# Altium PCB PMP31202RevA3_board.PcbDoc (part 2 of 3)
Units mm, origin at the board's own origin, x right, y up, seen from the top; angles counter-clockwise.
Board outline 156.21 x 130.81 mm, 4 copper layers (Top Layer, Layer 2, Layer 3, Bottom Layer), stack 1.671 mm thick; 198 components, 74 nets, 489 pads, 691 vias.
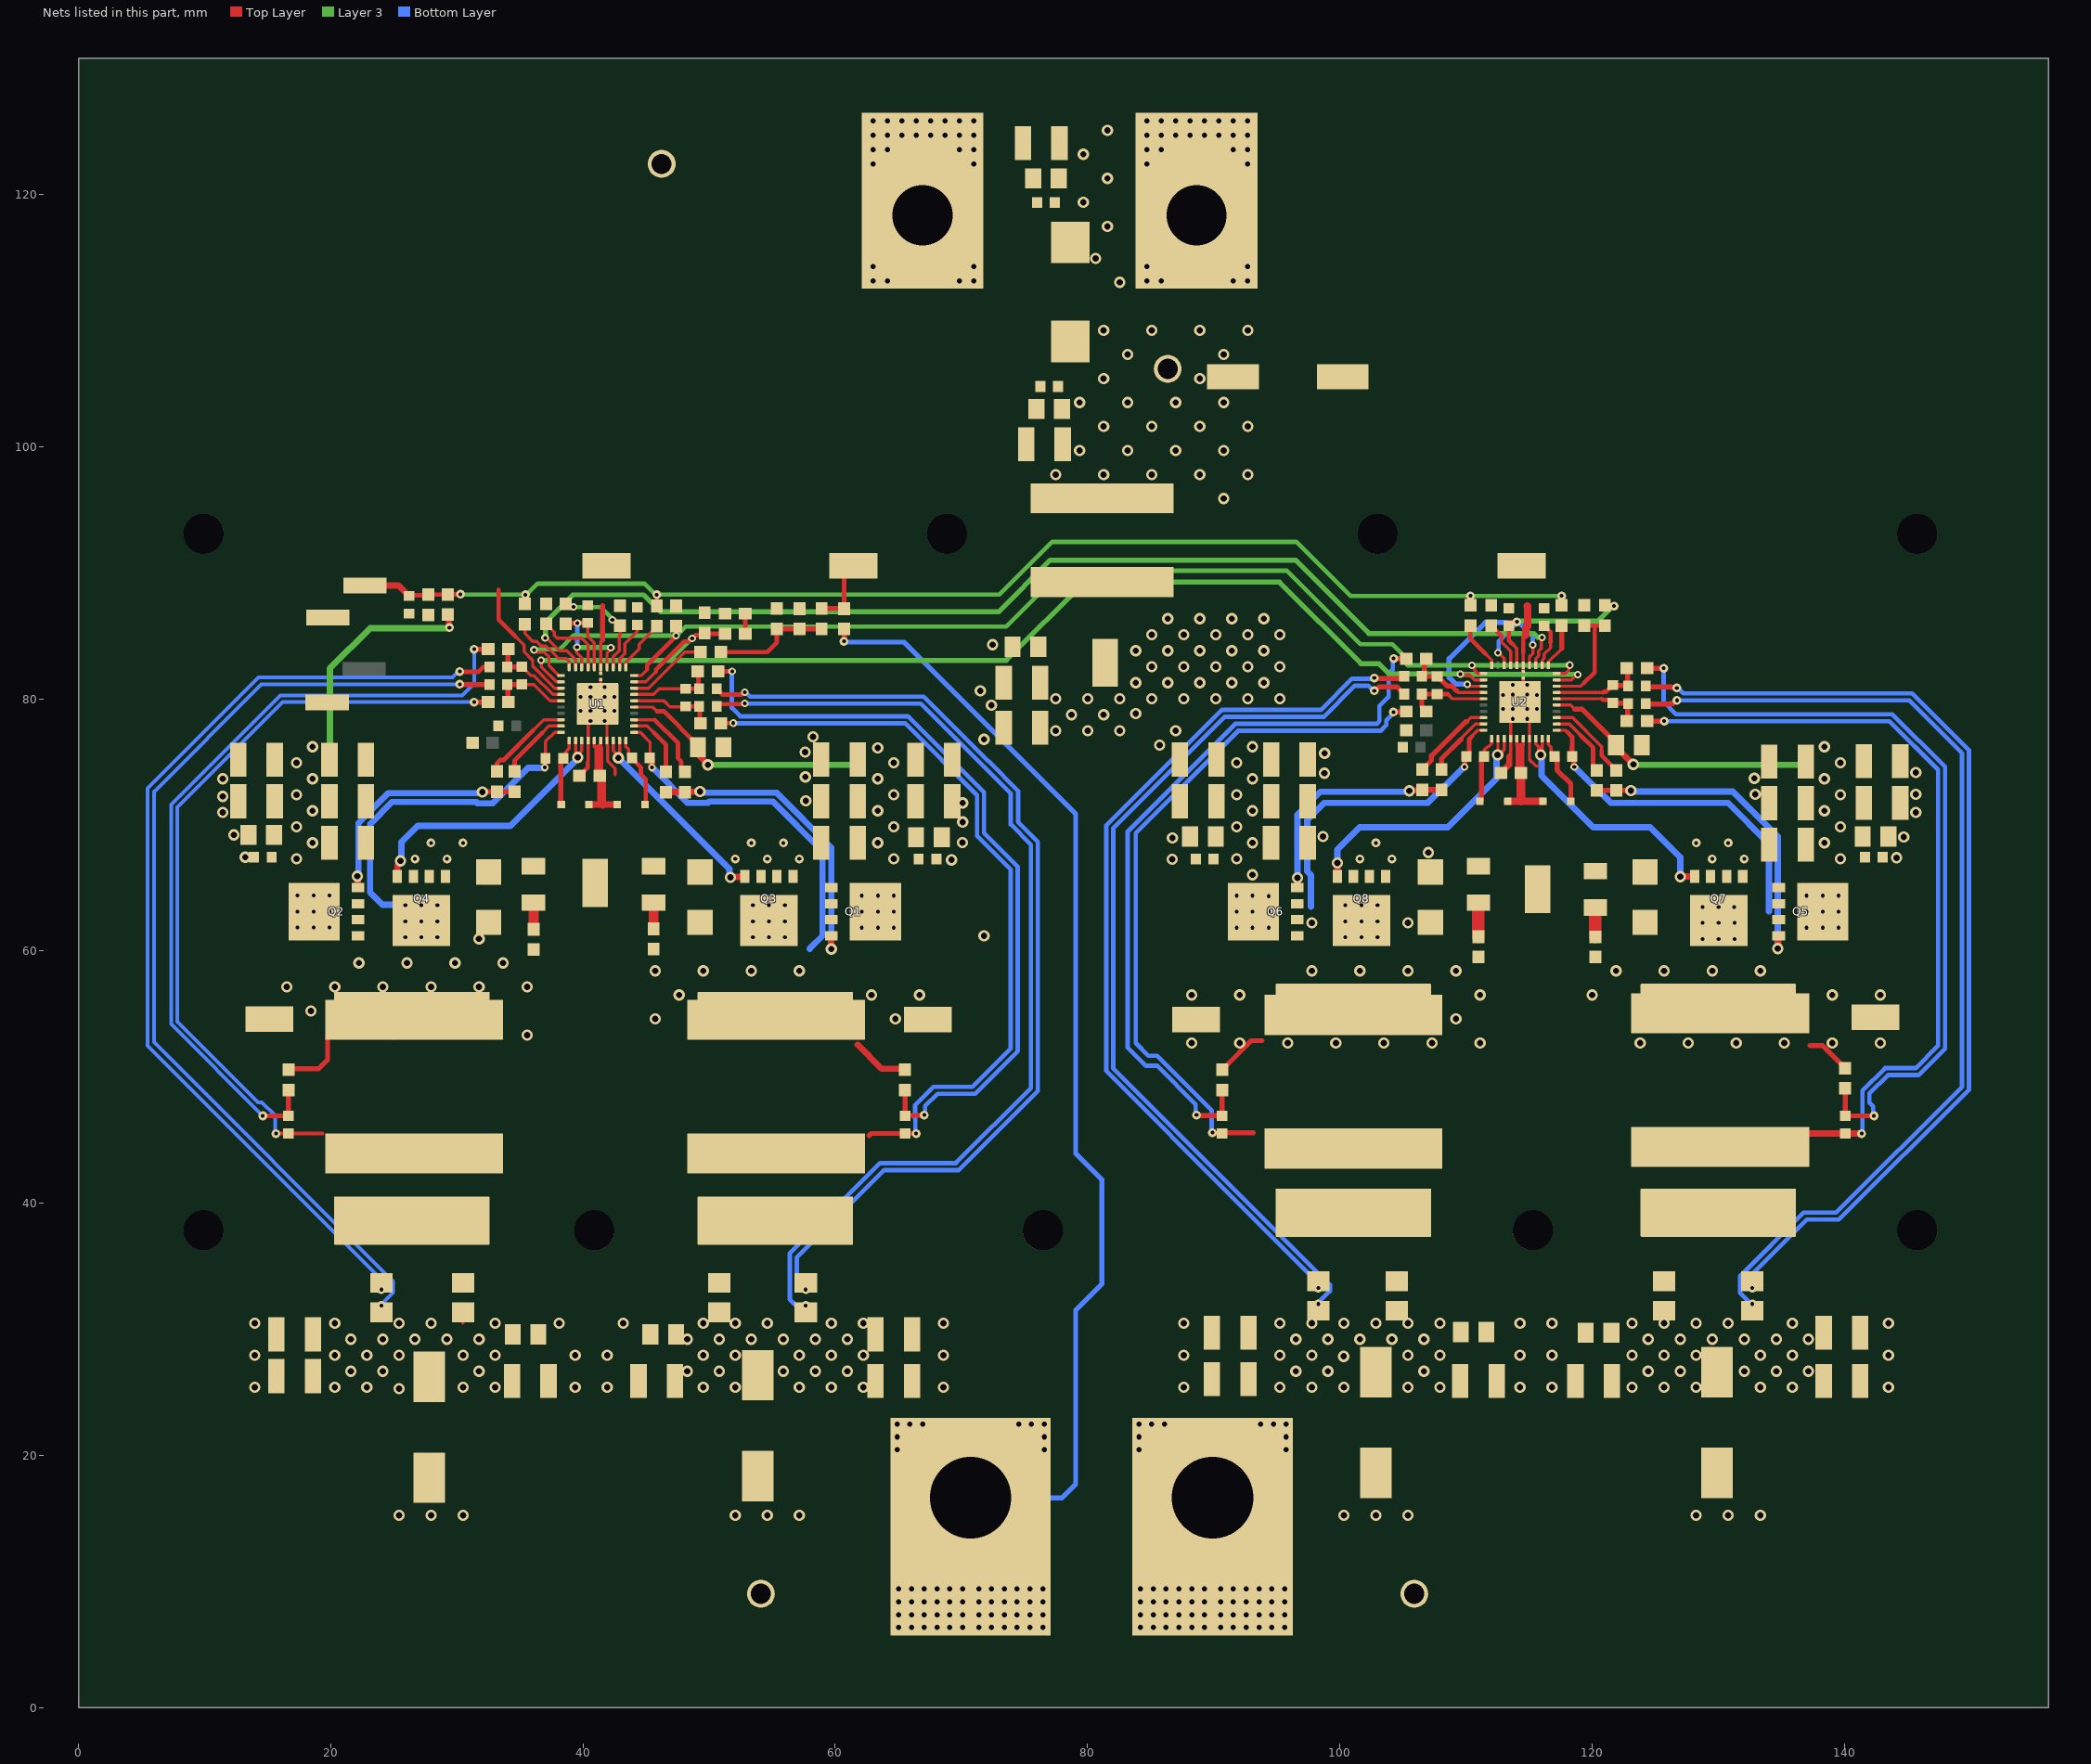
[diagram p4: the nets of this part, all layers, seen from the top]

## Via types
v1: diameter 0.9, hole 0.5, Top Layer to Bottom Layer, tented bottom, 173 vias
v2: diameter 0.813, hole 0.406, Top Layer to Bottom Layer, 172 vias
v3: diameter 0.9, hole 0.5, Top Layer to Bottom Layer, 82 vias
v4: diameter 0.9, hole 0.5, Top Layer to Bottom Layer, tented both sides, 73 vias
v5: diameter 0.7, hole 0.3, Top Layer to Bottom Layer, 69 vias
v6: diameter 0.7, hole 0.3, Top Layer to Bottom Layer, tented bottom, 28 vias
v7: diameter 0.6, hole 0.3, Top Layer to Bottom Layer, tented both sides, 26 vias
v8: diameter 0.7, hole 0.3, Top Layer to Bottom Layer, tented both sides, 24 vias
v9: diameter 0.6, hole 0.3, Top Layer to Bottom Layer, 24 vias
v10: diameter 0.9, hole 0.5, Top Layer to Bottom Layer, tented top, 13 vias
v11: diameter 0.7/0.7/0.7/0.7 (per signal layer), hole 0.3, Top Layer to Bottom Layer, tented bottom, 2 vias
v12: diameter 0.7/0.7/0.7/0.7 (per signal layer), hole 0.3, Top Layer to Bottom Layer, tented both sides, 2 vias
v13: diameter 0.7, hole 0.3, Top Layer to Bottom Layer, tented top, 1 vias
v14: diameter 0.7, hole 0.4, Top Layer to Bottom Layer, tented both sides, 1 vias
v15: diameter 0.6, hole 0.3, Top Layer to Bottom Layer, tented top, 1 vias

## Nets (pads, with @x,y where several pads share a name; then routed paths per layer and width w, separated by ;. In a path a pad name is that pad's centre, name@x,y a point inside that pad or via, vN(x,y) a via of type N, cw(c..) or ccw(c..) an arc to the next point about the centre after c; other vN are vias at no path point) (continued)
AGND1: C13.1 C47.2 C48.2 C49.2 C50.2 C52.2 NT1.2 R25.2 R29.1 R30.1 TP6.1 U1.3 U1.35 | length 15.6
  Top Layer w0.25: 34.627,84.949 35.317,84.26 35.317,83.751 36.007,83.061 36.007,82.588 37.749,80.846 U1.3@38.248,80.846 ; NT1.2@41.402,82.042 U1.35@41.398,82.496 41.398,84.523 41.533,84.658
  Top Layer w0.35: 33.298,88.666 33.298,86.279 34.627,84.949
  Top Layer w0.4: 41.533,84.658 41.533,87.4
AGND2: C55.1 C89.2 NT2.2 R54.2 R55.1 TP8.1 U2.35 | length 5.3
  Top Layer w0.25: 114.55,83.656 U2.35@114.55,82.656 114.55,82.169 NT2.2@114.554,82.169
  Top Layer w0.35: 114.55,83.656 114.55,84.861 114.753,85.064
  Top Layer w0.6: 114.753,85.064 114.753,85.611 114.896,85.754 114.896,87.341 114.875,87.362
COMP: C47.1 R28.2 U1.2 U1.29 U2.2 U2.29 | length 105.7
  Top Layer w0.25: v7(36.673,83.061) 36.703,83.031 36.703,82.528 37.886,81.346 U1.2@38.248,81.346 ; U1.29@44.048,81.346 44.974,81.346 45.777,82.149 ; v7(109.577,81.965) 109.644,81.898 110.286,81.898 110.678,81.506 U2.2@111.4,81.506 ; U2.29@117.2,81.506 118.368,81.506 118.777,81.915 v7(118.872,81.915)
  Top Layer w0.35: 45.777,82.149 45.777,82.321 48.014,84.558 48.356,84.558 48.594,84.796 v7(48.648,84.796) 48.664,84.796 48.918,85.05 49.469,85.05 C47.1@49.643,85.224 49.714,85.153 51.245,85.153 R28.2@51.26,85.168
  Layer 3 w0.4: v7(36.673,83.061) 46.859,83.061 ; v7(48.648,84.796) 48.594,84.796 46.859,83.061 ; v7(118.872,81.915) 118.847,81.94 109.602,81.94 v7(109.577,81.965) 103.927,81.965 103.092,82.8 101.688,82.8 95.23,89.258 79.755,89.258 73.558,83.061 46.859,83.061
NetC1_1: C1.1 C2.2 C3.2 J1.1 L1.1
  other v1: 81.577,121.285 79.672,123.19 81.577,125.095
  other v2: 84.709,113.157 85.852,113.157 91.567,113.157 92.71,113.157 84.709,114.3 92.71,114.3 84.709,122.428 92.71,122.428 84.709,123.571 85.852,123.571 91.567,123.571 92.71,123.571 84.709,124.714 85.852,124.714 86.995,124.714 88.138,124.714 89.281,124.714 90.424,124.714 91.567,124.714 92.71,124.714 84.709,125.857 85.852,125.857 86.995,125.857 88.138,125.857 89.281,125.857 90.424,125.857 91.567,125.857 92.71,125.857
  other v4: 82.55,113.03 80.645,114.935 81.577,117.475 79.672,119.38
NetC4_2: C4.2 C5.2 C6.1 C7.1 L1.2 L2.1 TP1.1
  other v1: 90.805,95.885 88.9,97.79 92.71,97.79 83.185,99.695 86.995,99.695 90.805,99.695 81.28,101.6 85.09,101.6 88.9,101.6 83.185,103.505 86.995,103.505 81.28,105.41 83.185,107.315 85.09,109.22 88.9,109.22
  other v4: 77.47,97.79 81.28,97.79 85.09,97.79 79.375,99.695 92.71,101.6 79.375,103.505 90.805,103.505 88.9,105.41 90.805,107.315 81.28,109.22 92.71,109.22
NetC29_1: C29.1 C32.1 D3.1 L3.2 Q1.1 Q1.2 Q1.3 Q3.5 R8.2 SW1.1 U1.21 | length 32.9
  Top Layer w0.25: U1.21@44.048,77.346 44.545,77.346 45.315,76.576 45.315,75.349 C29.1@45.277,75.311
  Top Layer w0.5: C29.1@45.315,75.349 45.427,75.237 45.427,74.615 45.466,74.576 v7(45.466,74.549) ; 61.775,52.58 63.696,50.659 65.457,50.659 R8.2@65.532,50.584
  Bottom Layer w0.5: v7(45.466,74.549) 45.493,74.549 48.301,71.741 49.9,71.741 50.024,71.864 55.028,71.864 58.989,67.903 58.989,61.214 57.975,60.2 57.975,60.16 ; v5(56.007,63.627) v5@56.035,63.627
  other v3: 45.72,54.61 64.77,54.61 47.625,56.515 62.865,56.515 66.675,56.515 45.72,58.42 49.53,58.42 53.34,58.42 57.15,58.42
  other v5: 53.467,61.087 54.737,61.087 56.007,61.087 53.467,62.357 54.737,62.357 56.007,62.357 53.467,63.627 54.737,63.627
NetC29_2: C29.2 D1.1 U1.20 | length 6.1
  Top Layer w0.25: U1.20@43.398,76.696 43.398,76.204 43.602,76 43.602,75.586 C29.2@43.877,75.311
  Top Layer w0.35: C29.2@44.102,75.086 C29.2@43.877,75.311 43.877,75.286 44.577,74.586 44.577,74.023 44.974,73.626 44.974,71.687 D1.1@44.915,71.628
NetC30_1: C30.1 C33.2 D4.1 L4.2 Q2.1 Q2.2 Q2.3 Q4.5 R9.2 SW2.1 U1.10 | length 42.7
  Top Layer w0.25: C30.1@37.023,75.297 37.023,76.627 37.742,77.346 U1.10@38.248,77.346
  Top Layer w0.4: R9.2@16.667,50.554 R9.2@16.637,50.584 16.712,50.659 19.016,50.659 19.742,51.386 19.742,53.161 21.132,54.551 L4.2@26.409,54.551 ; L4.2@25.019,53.161 L4.2@26.409,54.551 ; L4.2@26.592,54.551 L4.2@26.409,54.551
  Top Layer w0.5: v7(36.957,74.549) 36.976,74.568 36.976,75.25 C30.1@37.023,75.297
  Bottom Layer w0.5: v5(25.908,63.627) 25.87,63.665 24.092,63.665 23.114,64.643 23.114,70.082 24.859,71.828 31.516,71.828 31.639,71.705 32.803,71.705 35.628,74.53 36.938,74.53 v7(36.957,74.549)
  other v3: 35.56,53.34 18.415,55.245 16.51,57.15 35.56,57.15 22.225,59.055 26.035,59.055 29.845,59.055 33.655,59.055
  other v5: 25.908,61.087 27.178,61.087 28.448,61.087 25.908,62.357 27.178,62.357 28.448,62.357 27.178,63.627 28.448,63.627
  other v10: 20.32,57.15 24.13,57.15 27.94,57.15 31.75,57.15 31.75,60.96
NetC30_2: C30.2 D2.1 U1.11 | length 5.4
  Top Layer w0.25: C30.2@38.423,75.297 38.598,75.472 38.598,75.772 38.898,76.072 U1.11@38.898,76.696
  Top Layer w0.4: D2.1@38.27,71.628 38.223,71.675 38.223,75.097 C30.2@38.423,75.297
NetC31_1: C31.1 R8.1 R15.2 | length 61.9
  Top Layer w0.35: R15.2@50.701,82.188 50.711,82.178 51.807,82.178 v7(51.816,82.169) ; C31.1@65.532,46.928 65.563,46.959 67.025,46.959 v8(67.056,46.99)
  Top Layer w0.4: C31.1@65.532,46.928 R8.1@65.532,48.984
  Bottom Layer w0.35: v7(51.816,82.169) 51.801,82.154 51.801,79.275 52.462,78.614 65.762,78.614 71.792,72.583 71.792,69.352 74.464,66.68 74.464,52.054 71.094,48.684 68.106,48.684 67.123,47.701 67.123,47.057 v8(67.056,46.99)
NetC31_2: C31.2 L3.1 R6.2 R11.2 R14.2 R61.2 | length 139.8
  Top Layer w0.35: R11.2@50.601,80.791 50.601,80.766 50.826,80.541 50.851,80.541 51.046,80.346 52.592,80.346 52.764,80.518 v7(52.832,80.518) ; R14.2@50.918,78.064 50.924,78.07 51.914,78.07 v7(51.92,78.077) ; v8(57.658,33.147) R6.2@57.658,34.212 ; C31.2@65.532,45.528 v8(66.411,45.528)
  Top Layer w0.4: 62.675,45.353 62.85,45.528 C31.2@65.532,45.528
  Bottom Layer w0.35: v7(51.92,78.077) 51.933,78.064 65.534,78.064 71.242,72.356 71.242,69.124 73.914,66.452 73.914,52.282 70.866,49.234 67.777,49.234 66.331,47.788 66.331,46.69 66.344,46.677 66.344,45.595 v8(66.411,45.528) ; v7(52.832,80.518) 52.898,80.518 53.237,80.179 67.01,80.179 72.134,75.055 72.146,75.055 74.492,72.709 74.492,70.241 76.067,68.665 76.067,48.905 69.792,42.63 63.881,42.63 56.938,35.687 56.938,33.962 57.658,33.242 v8(57.658,33.147)
NetC32_2: C32.2 R18.2 | length 2.1
  Top Layer w0.8: C32.2@45.593,61.76 R18.2@45.593,63.828
NetC33_1: C33.1 R19.1 | length 2.1
  Top Layer w0.8: C33.1@36.068,61.722 R19.1@36.068,63.828
NetC34_1: C34.1 R9.1 R16.2 | length 63.6
  Top Layer w0.4: v6(14.605,46.928) C34.1@16.637,46.928 R9.1@16.637,48.984 ; v8(31.369,83.933) R16.2@32.478,83.933
  Bottom Layer w0.3: v6(14.605,46.928) 7.332,54.201 7.332,71.615 15.983,80.266 30.418,80.266 31.369,81.217 v8(31.369,83.933)
NetC34_2: C34.2 L4.1 R7.1 R12.2 R17.2 R71.1 | length 140.8
  Top Layer w0.3: v6(15.646,45.528) C34.2@16.637,45.528 19.35,45.528 ; v8(24.003,33.147) R7.1@24.003,34.212
  Top Layer w0.35: v8(30.226,82.169) 30.257,82.138 31.68,82.138 32.078,82.536 R12.2@32.578,82.536
  Top Layer w0.4: v8(31.369,79.742) R17.2@32.478,79.742 ; R12.2@32.538,82.496 R12.2@32.578,82.536
  Bottom Layer w0.3: v6(15.646,45.528) 15.57,45.605 15.57,46.953 14.517,48.006 14.234,48.006 7.832,54.408 7.832,71.408 16.166,79.742 v8(31.369,79.742) ; v8@23.936,33.214 23.936,34.02 5.469,52.487 5.469,72.908 14.264,81.703 29.652,81.703 30.118,82.169 v8(30.226,82.169)
  Bottom Layer w0.35: v8@23.936,33.214 v8(24.003,33.147)
NetC45_1: C45.1 R10.1 R14.1 U1.26 | length 6.7
  Top Layer w0.25: U1.26@44.048,79.846 46.422,79.846 46.889,79.379 48.105,79.379 C45.1@48.123,79.397
  Top Layer w0.35: C45.1@48.123,79.397 48.125,79.396 49.199,79.396 R10.1@49.201,79.394 49.26,79.335 49.26,78.123 R14.1@49.318,78.064
NetC45_2: C45.2 R11.1 R15.1 U1.27 | length 6.8
  Top Layer w0.25: U1.27@44.048,80.346 45.581,80.346 46.032,80.797 C45.2@48.123,80.797
  Top Layer w0.35: C45.2@48.123,80.797 48.126,80.794 R11.1@49.198,80.794 ; R15.1@49.101,82.188 49.151,82.138 49.151,80.841 R11.1@49.198,80.794 ; R11.1@49.201,80.791 R11.1@49.198,80.794
NetC46_1: C46.1 R13.1 R17.1 U1.5 | length 6.2
  Top Layer w0.25: C46.1@35.15,81.146 35.157,81.139 36.093,81.139 37.386,79.846 U1.5@38.248,79.846
  Top Layer w0.4: R17.1@34.078,79.742 34.028,79.792 34.028,81.089 R13.1@33.978,81.139 33.982,81.142 35.147,81.142 C46.1@35.15,81.146
NetC46_2: C46.2 R12.1 R16.1 U1.4 | length 6.6
  Top Layer w0.25: C46.2@35.15,82.546 35.175,82.546 35.875,81.846 36.113,81.846 37.613,80.346 U1.4@38.248,80.346
  Top Layer w0.4: R12.1@33.978,82.536 R12.1@33.983,82.541 ; R16.1@34.078,83.933 34.028,83.883 34.028,82.586 R12.1@33.983,82.541 ; C46.2@35.175,82.546 35.17,82.541 R12.1@33.983,82.541
NetC48_1: C48.1 R22.1 R27.1 R29.2 | length 9.4
  Top Layer w0.35: R22.1@50.917,83.712 54.61,83.712 55.372,84.474 R29.2@55.372,85.56 R29.2@55.379,85.553 ; C48.1@57.147,85.553 C48.1@57.154,85.546 ; C48.1@57.161,85.553 C48.1@57.154,85.546 ; C48.1@57.164,85.536 C48.1@57.154,85.546 ; R27.1@58.91,85.553 R27.1@58.917,85.56
  Top Layer w0.4: R29.2@55.379,85.553 C48.1@57.147,85.553 ; C48.1@57.161,85.553 R27.1@58.91,85.553
NetC50_1: C50.1 U1.32 | length 4
  Top Layer w0.25: U1.32@42.898,82.496 42.898,83.174 43.313,83.589 43.313,84.378 44.302,85.367 C50.1@44.302,85.867
NetC52_1: C52.1 R28.1 | length 1.6
  Top Layer w0.35: R28.1@52.86,85.168 C52.1@52.86,86.76
NetC71_1: C71.1 C75.1 D7.1 L5.2 Q5.1 Q5.2 Q5.3 Q7.5 R39.2 SW3.1 U2.21 | length 30.8
  Top Layer w0.25: U2.21@117.2,77.506 117.914,77.506 118.077,77.343
  Top Layer w0.35: 118.077,77.343 118.429,76.991 118.429,76.177
  Top Layer w0.4: 118.429,76.177 C71.1@118.429,75.438 118.566,75.301 118.566,74.647 v7(118.604,74.609) ; 137.287,52.489 138.303,52.489 139.781,51.011 139.806,51.011 140.081,50.736 R39.2@140.081,50.711
  Bottom Layer w0.5: v7(118.604,74.609) 118.631,74.609 121.485,71.755 130.782,71.755 134.034,68.503 134.034,63.13 ; v6(131.318,60.96) v6@131.356,60.998
  other v3: 139.065,52.705 142.875,52.705 120.015,56.515 139.065,56.515 142.875,56.515 121.92,58.42 125.73,58.42 129.54,58.42 133.35,58.42
  other v6: 128.778,60.96 130.048,60.96 128.778,62.23 130.048,62.23 131.318,62.23 128.778,63.5 130.048,63.5 131.286,63.5
  other v10: 123.825,52.705 127.635,52.705 131.445,52.705 135.255,52.705
NetC71_2: C71.2 D5.1 U2.20 | length 5.7
  Top Layer w0.25: U2.20@116.55,76.856 116.55,76.382 116.754,76.178 116.754,75.713 C71.2@117.029,75.438
  Top Layer w0.4: C71.2@117.029,75.438 117.229,75.238 117.229,74.358 118.327,73.26 118.327,71.888 D5.1@118.321,71.882
NetC72_1: C72.1 C76.2 D8.1 L6.2 Q6.1 Q6.2 Q6.3 Q8.5 R40.2 SW4.1 U2.10 | length 29.2
  Top Layer w0.25: 110.498,77.031 110.498,77.07 110.934,77.506 U2.10@111.4,77.506
  Top Layer w0.35: R40.2@90.678,50.584 90.678,50.609 90.978,50.909 R40.2@91.003,50.909 ; 92.977,52.883 93.853,52.883 ; C72.1@110.044,75.438 110.269,75.663 110.269,76.802 110.498,77.031
  Top Layer w0.4: R40.2@91.003,50.909 92.977,52.883 ; v7(109.888,74.609) 109.926,74.647 109.926,75.32 C72.1@110.044,75.438
  Bottom Layer w0.5: 97.712,63.5 97.712,66.021 97.418,66.315 97.418,70.402 98.771,71.755 107.007,71.755 109.861,74.609 v7(109.888,74.609)
  other v3: 88.265,52.705 92.075,52.705 111.125,52.705 109.22,54.61 88.265,56.515 92.075,56.515 111.125,56.515 97.79,58.42 101.6,58.42 105.41,58.42 109.22,58.42 97.79,62.23 105.41,62.23
  other v5: 100.457,61.087 101.727,61.087 102.997,61.087 100.457,62.357 101.727,62.357 102.997,62.357 100.457,63.627 101.727,63.627 102.997,63.627
  other v10: 95.885,52.705 99.695,52.705 103.505,52.705 107.315,52.705
NetC72_2: C72.2 D6.1 U2.11 | length 5.4
  Top Layer w0.25: C72.2@111.444,75.438 111.473,75.467 111.473,75.963 111.71,76.2 111.793,76.2 112.05,76.457 U2.11@112.05,76.856
  Top Layer w0.4: D6.1@111.125,71.882 111.244,72.001 111.244,75.238 C72.2@111.444,75.438
NetC74_1: C74.1 R39.1 R46.2 | length 64.6
  Top Layer w0.4: R46.2@124.371,82.423 v8(125.692,82.423) ; R39.1@140.081,49.111 C74.1@140.081,46.928 v6(142.367,46.928)
  Bottom Layer w0.35: v8(125.692,82.423) 125.692,79.756 126.666,78.782 143.822,78.782 147.997,74.607 147.997,52.261 145.897,50.161 143.47,50.161 142.011,48.702 142.011,47.959 142.3,47.67 142.3,46.995 v6(142.367,46.928)
NetC74_2: C74.2 L5.1 R37.2 R42.2 R45.2 R371.2 | length 142.7
  Top Layer w0.4: R42.2@124.271,81.006 124.322,80.955 126.291,80.955 126.323,80.923 126.674,80.923 v8(126.731,80.866) ; R45.2@124.371,78.232 v8(125.73,78.232)
  Top Layer w0.5: v6(132.715,33.274) R37.2@132.715,34.339 ; L5.1@136.244,45.528 C74.2@140.081,45.528 v6(141.394,45.528)
  Bottom Layer w0.35: v8(125.73,78.232) 143.594,78.232 147.447,74.379 147.447,52.489 145.669,50.711 143.242,50.711 141.461,48.93 141.461,45.595 v6(141.394,45.528) ; v8(126.731,80.866) 126.826,80.866 127.259,80.433 145.389,80.433 149.902,75.92 149.902,49.018 139.584,38.699 137.033,38.699 132.782,34.448 132.782,33.341 v6(132.715,33.274)
NetC75_2: C75.2 R49.2 | length 2.3
  Top Layer w1: C75.2@120.271,61.125 R49.2@120.271,63.447
NetC76_1: C76.1 R50.1 | length 2.7
  Top Layer w1: C76.1@110.998,61.129 R50.1@110.998,63.828
NetC77_1: C77.1 R40.1 R47.2 | length 59.4
  Top Layer w0.35: v6(88.646,46.99) v6@88.677,46.959 ; C77.1@90.647,46.959 C77.1@90.678,46.928
  Top Layer w0.4: v6@88.677,46.959 C77.1@90.647,46.959 ; C77.1@90.678,46.928 R40.1@90.678,48.984 ; v8(104.277,83.204) 104.287,83.195 105.268,83.195 R47.2@105.278,83.185
  Bottom Layer w0.35: v6(88.646,46.99) 88.579,47.057 88.579,47.837 85.507,50.909 84.6,50.909 83.185,52.324 83.185,69.485 91.72,78.02 102.95,78.02 103.155,78.225 103.155,79.434 103.886,80.165 103.886,82.006 104.21,82.33 104.21,83.137 v8(104.277,83.204)
NetC77_2: C77.2 L6.1 R38.1 R43.2 R48.2 R381.1 | length 129.1
  Top Layer w0.35: v6(89.916,45.593) v6@89.948,45.561 ; C77.2@90.646,45.561 C77.2@90.678,45.528 C77.2@90.721,45.571 ; v8(98.298,33.274) R38.1@98.298,34.339 ; v6(102.743,81.661) 102.8,81.604 v6@102.81,81.594 ; R43.2@104.93,81.594 R43.2@105.124,81.788
  Top Layer w0.4: v6@89.948,45.561 C77.2@90.646,45.561 ; C77.2@90.721,45.571 93.155,45.571 ; v6@102.8,81.604 104.162,81.604 104.171,81.594 R43.2@104.93,81.594 ; v8(104.267,78.957) 104.285,78.975 105.259,78.975 R48.2@105.278,78.994
  Bottom Layer w0.35: v6(89.916,45.593) 89.849,45.66 89.849,47.344 85.504,51.689 84.836,51.689 83.82,52.705 83.82,69.342 91.948,77.47 103.257,77.47 103.705,77.918 103.705,78.3 104.267,78.862 v8(104.267,78.957) ; v8(98.298,33.274) 98.298,33.369 98.044,33.623 98.044,33.929 91.791,40.183 81.492,50.481 81.492,69.969 90.643,79.12 98.512,79.12 100.986,81.594 102.676,81.594 v6(102.743,81.661) ; v6@102.656,81.788 v6@102.743,81.788
NetC87_1: C87.1 R41.1 R45.1 U2.26 | length 7.3
  Top Layer w0.25: U2.26@117.2,80.006 120.777,80.006
  Top Layer w0.3: 120.777,80.006 120.867,79.916
  Top Layer w0.35: 120.867,79.916 121.441,79.916 C87.1@121.666,79.691
  Top Layer w0.4: C87.1@121.666,79.691 121.697,79.66 122.84,79.66 R41.1@122.871,79.629 122.821,79.579 122.821,78.282 R45.1@122.771,78.232
NetC87_2: C87.2 R42.1 R46.1 U2.27 | length 7.3
  Top Layer w0.25: U2.27@117.2,80.506 120.867,80.506
  Top Layer w0.3: 120.867,80.506 120.917,80.556
  Top Layer w0.35: 120.917,80.556 121.106,80.556 121.641,81.091 C87.2@121.666,81.091
  Top Layer w0.4: C87.2@121.666,81.091 121.708,81.048 R42.1@122.828,81.048 ; R46.1@122.771,82.423 122.821,82.373 122.821,81.056 R42.1@122.828,81.048 ; R42.1@122.871,81.006 R42.1@122.828,81.048
NetC88_1: C88.1 R44.1 R48.1 U2.5 | length 6.6
  Top Layer w0.25: 108.573,80.376 108.943,80.006 U2.5@111.4,80.006
  Top Layer w0.4: R48.1@106.878,78.994 106.853,78.994 106.578,79.269 106.578,79.294 106.515,79.357 106.515,80.367 R44.1@106.524,80.376 C88.1@107.729,80.376 108.573,80.376
NetC88_2: C88.2 R43.1 R47.1 U2.4 | length 7
  Top Layer w0.25: 109.255,80.645 109.394,80.506 U2.4@111.4,80.506
  Top Layer w0.4: R47.1@106.878,83.185 106.701,83.008 106.701,81.965 R43.1@106.524,81.788 106.524,81.776 C88.2@107.729,81.776 107.754,81.776 108.52,81.01 108.89,81.01 109.255,80.645
NetC89_1: C89.1 U2.32 | length 3.6
  Top Layer w0.25: U2.32@116.05,82.656 116.05,83.06 116.216,83.226 116.216,83.556 116.713,84.053 116.713,84.483
  Top Layer w0.35: C89.1@116.205,85.787 116.23,85.787 116.725,85.292 116.725,84.495 116.713,84.483
NetNWA_1: NWA.1 R23.1 R27.2 | length 5.5
  Top Layer w0.35: R27.2@58.917,87.16 R27.2@58.924,87.153 ; R23.1@60.699,87.153 R23.1@60.706,87.146
  Top Layer w0.4: R27.2@58.924,87.153 60.699,87.153 60.699,89.826 NWA.1@61.431,90.558
NetQ1_4: Q1.4 R2.1 R4.1 | length 24
  Top Layer w0.5: R2.1@46.576,72.609 R4.1@48.088,72.609 48.104,72.625 49.26,72.625 v4(49.276,72.641) ; v1(59.689,60.163) Q1.4@59.689,61.214
  Bottom Layer w0.5: v4(49.276,72.641) 49.353,72.564 55.318,72.564 59.689,68.193 v1(59.689,60.163)
NetQ2_4: Q2.4 R3.2 R5.2 | length 18.6
  Top Layer w0.4: v1(32.012,72.605) 32.03,72.622 33.149,72.622 R5.2@33.167,72.64 R3.2@34.581,72.641
  Top Layer w0.5: v1(22.095,65.935) 22.128,65.902 22.128,65.057 Q2.4@22.162,65.024
  Bottom Layer w0.4: v1(22.095,65.935) v1@22.191,66.031
  Bottom Layer w0.5: v1@22.191,66.031 22.191,70.149 24.569,72.528 31.935,72.528 v1(32.012,72.605)
NetQ3_4: Q3.4 U1.18 U1.19 | length 17.3
  Top Layer w0.25: U1.18@42.398,76.696 42.398,76.006 42.398,75.888 42.799,75.487 v4(42.799,75.311) 42.898,75.41 U1.19@42.898,76.696
  Top Layer w0.5: v1(51.689,65.849) 51.721,65.882 52.8,65.882 Q3.4@52.832,65.914
  Bottom Layer w0.5: v4(42.799,75.311) 51.612,66.498 51.612,65.926 v1(51.689,65.849)
NetQ4_4: Q4.4 U1.12 U1.13 | length 22.5
  Top Layer w0.25: U1.12@39.398,76.696 39.398,75.65 v4@39.573,75.475 ; v4(39.573,75.357) v4@39.573,75.475 ; U1.13@39.898,76.696 39.898,75.858 39.573,75.533 v4@39.573,75.475
  Top Layer w0.5: Q4.4@25.273,65.913 25.284,65.924 25.284,66.802 25.527,67.046 v1(25.527,67.154)
  Bottom Layer w0.5: v1@25.635,67.154 v1(25.527,67.154) 25.604,67.231 25.604,68.644 26.892,69.932 34.233,69.932 39.573,75.272 v4(39.573,75.357)
NetQ5_4: Q5.4 R33.1 R35.1 | length 25.8
  Top Layer w0.4: R33.1@120.396,72.733 R35.1@121.92,72.733 v1(123.096,72.733)
  Top Layer w0.5: v1(134.734,60.192) 134.772,60.23 134.772,61.176 Q5.4@134.81,61.214
  Bottom Layer w0.5: v1(123.096,72.733) 123.173,72.656 131.171,72.656 134.734,69.093 v1(134.734,60.192)
NetQ6_4: Q6.4 R34.2 R36.2 | length 18
  Top Layer w0.5: Q6.4@96.648,65.024 v1(96.648,65.813) ; v1(105.528,72.709) 105.566,72.746 106.515,72.746 R36.2@106.553,72.784 R34.2@108.077,72.784
  Bottom Layer w0.5: v1(96.648,65.813) 96.648,70.81 98.47,72.632 105.451,72.632 v1(105.528,72.709)
NetQ7_4: Q7.4 U2.18 U2.19 | length 20.9
  Top Layer w0.25: U2.18@115.55,76.856 115.55,76.428 115.801,76.177 ; v4@115.801,75.689 v4(115.925,75.565) 116.049,75.689 116.049,76.22 ; 116.05,76.22 U2.19@116.05,76.856
  Top Layer w0.3: v4@115.801,75.689 115.801,76.177
  Top Layer w0.5: v1(127,65.894) 127,65.914 Q7.4@128.143,65.914
  Bottom Layer w0.5: v4(115.925,75.565) 116.002,75.488 116.002,73.916 120.105,69.813 124.624,69.813 127,67.437 v1(127,65.894)
NetQ8_4: Q8.4 U2.12 U2.13 | length 21.9
  Top Layer w0.25: U2.12@112.55,76.856 112.55,75.593 v4(112.522,75.565) 112.652,75.565 113.05,75.963 U2.13@113.05,76.856
  Top Layer w0.5: Q8.4@99.822,65.914 v1(99.822,66.978)
  Bottom Layer w0.5: v1(99.822,66.978) 99.822,68.043 101.592,69.813 108.573,69.813 112.445,73.685 112.445,75.488 v4(112.522,75.565)
NetR2_2: R2.2 U1.22 | length 5.3
  Top Layer w0.25: U1.22@44.048,77.846 45.085,77.846 45.592,77.339
  Top Layer w0.35: 45.592,77.339 46.576,76.355 R2.2@46.576,74.209
NetR3_1: R3.1 U1.9 | length 5.7
  Top Layer w0.25: 36.793,77.346 37.293,77.846 U1.9@38.248,77.846
  Top Layer w0.35: R3.1@34.581,74.241 34.581,75.134 36.793,77.346
NetR4_2: R4.2 U1.23 | length 6.8
  Top Layer w0.25: U1.23@44.048,78.346 45.658,78.346 45.678,78.327
  Top Layer w0.35: 45.678,78.327 47.526,76.478 47.526,75.297 47.756,75.067 47.756,74.959 47.788,74.926 47.788,74.509 R4.2@48.088,74.209
NetR5_1: R5.1 U1.8 | length 7.2
  Top Layer w0.25: 36.068,77.527 36.887,78.346 U1.8@38.248,78.346
  Top Layer w0.35: R5.1@33.167,74.24 33.158,74.24 33.158,74.878 33.427,75.148 33.689,75.148 36.068,77.527
NetR20_2: R20.2 U1.31 | length 4.3
  Top Layer w0.25: U1.31@43.398,82.496 43.398,82.906 44.453,83.961 44.453,84.344 45.851,85.742 R20.2@45.851,85.767
NetR21_1: R21.1 U1.40 | length 5.7
  Top Layer w0.25: R21.1@35.388,85.927 35.388,85.177 36.007,84.558 36.317,84.558 36.675,84.2 37.068,84.2 37.218,84.05 37.222,84.05 37.648,83.624 38.064,83.208 38.677,83.208 38.898,82.987 U1.40@38.898,82.496
NetR22_2: R22.2 U1.28 | length 6.5
  Top Layer w0.25: U1.28@44.048,80.846 45.182,80.846 48.048,83.712 R22.2@49.317,83.712
NetR24_1: R24.1 R25.1 U1.33 | length 8.6
  Top Layer w0.25: U1.33@42.398,82.496 42.398,83.359 42.863,83.824 42.863,84.983 42.93,85.05 R25.1@42.93,85.8
  Top Layer w0.35: R24.1@38.608,87.541 38.801,87.348 39.195,87.348 v7(39.243,87.3) ; v7(42.316,86.258) 42.364,86.211 42.544,86.211 42.93,85.825 R25.1@42.93,85.8
  Layer 3 w0.25: v7(39.243,87.3) v7@39.268,87.274 ; v7(42.316,86.258) v7@42.316,86.341
  Layer 3 w0.35: v7@39.268,87.274 41.383,87.274 v7@42.316,86.341
NetR30_2: R30.2 U1.37 | length 6
  Top Layer w0.25: R30.2@37.084,85.941 37.084,85.916 37.723,85.277 37.723,85.017 37.93,84.81 39.881,84.81 40.398,84.293 U1.37@40.398,82.496
NetR33_2: R33.2 U2.22 | length 5.6
  Top Layer w0.25: U2.22@117.2,78.006 118.216,78.006 119.096,77.125
  Top Layer w0.35: 119.096,77.125 120.096,76.126 120.096,74.633 R33.2@120.396,74.333
NetR34_1: R34.1 U2.9 | length 5.4
  Top Layer w0.25: 109.633,76.802 109.633,76.873 110.766,78.006 U2.9@111.4,78.006
  Top Layer w0.4: R34.1@108.077,74.384 108.077,75.246 109.633,76.802
NetR35_2: R35.2 U2.23 | length 6.9
  Top Layer w0.25: U2.23@117.2,78.506 118.473,78.506 120.777,76.202 120.777,75.913
  Top Layer w0.35: 120.777,75.913 120.777,75.501 121.92,74.358 R35.2@121.92,74.333
NetR36_1: R36.1 U2.8 | length 6.8
  Top Layer w0.25: 110.081,78.181 110.406,78.506 U2.8@111.4,78.506
  Top Layer w0.4: R36.1@106.553,74.384 106.553,74.409 107.278,75.134 107.278,75.488 109.971,78.181 110.081,78.181
NetR51_2: R51.2 U2.31 | length 3.6
  Top Layer w0.25: U2.31@116.55,82.656 116.55,82.923 117.602,83.975 117.602,83.995
  Top Layer w0.4: 117.602,83.995 R51.2@117.602,85.814
NetR52_1: R52.1 U2.40 | length 3.9
  Top Layer w0.25: 111.575,83.566 111.582,83.566 112.05,83.098 U2.40@112.05,82.656
  Top Layer w0.35: R52.1@110.363,85.814 110.363,84.778 111.575,83.566
NetR53_1: R53.1 R54.1 U2.28 | length 8.8
  Top Layer w0.25: U2.28@117.2,81.006 119.123,81.006 119.38,81.263
  Top Layer w0.35: 119.38,81.263 120.218,82.101 120.218,85.814 ; R54.1@119.38,85.814 120.218,85.814 ; R53.1@121.031,85.814 120.218,85.814
NetR55_2: R55.2 U2.37 | length 3.8
  Top Layer w0.25: R55.2@112.014,85.789 R55.2@112.014,85.814 ; 112.845,84.958 112.845,84.483 113.55,83.778 U2.37@113.55,82.656
  Top Layer w0.35: R55.2@112.014,85.789 112.845,84.958
PGND: C1.2 C2.1 C3.1 C4.1 C5.1 C6.2 C7.2 C8.1 C9.2 C10.2 C11.2 C12.2 C14.2 C15.2 C16.2 C17.2 C18.2 C19.2 C20.1 C21.1 C22.1 C23.1 C24.2 C25.2 C26.2 C27.2 C28.2 C35.2 C36.2 C37.2 C38.2 C39.2 C40.1 C41.1 C42.2 C43.2 C44.2 C51.2 C53.2 C54.2 C56.2 C57.2 C58.2 C59.2 C60.2 C61.2 C62.1 C63.1 C64.1 C65.1 C66.2 C67.2 C68.2 C69.2 C70.2 C73.2 C78.2 C79.2 C80.2 C81.2 C82.1 C83.1 C84.2 C85.2 C86.2 D3.2 D4.2 D7.2 D8.2 J2.1 J3.1 J5.1 J6.1 NT1.1 NT2.1 Q3.1 Q3.2 Q3.3 Q4.1 Q4.2 Q4.3 Q7.1 Q7.2 Q7.3 Q8.1 Q8.2 Q8.3 R1.1 R18.1 R19.2 R31.1 R32.1 R49.1 R50.2 TP3.1 TP5.1 TP7.1 TP9.1 U1.14 U1.17 U1.41 U2.14 U2.17 U2.41 | length 21.1
  Top Layer w0.25: 40.368,74.959 40.398,74.989 U1.14@40.398,76.696 U1.41@40.398,78.346 ; U1.41@41.148,79.596 U1.41@41.406,79.854 ; 41.404,81.247 41.404,81.518 NT1.1@41.406,81.52 ; U1.41@41.898,78.346 U1.17@41.898,76.696 41.898,76.359 41.948,76.309 41.948,75.066 42.544,74.47 42.544,73.991 ; 113.444,75.407 113.55,75.513 U2.14@113.55,76.856 U2.41@113.55,78.306 ; v9(113.741,79.197) U2.41@114.3,79.756 ; U2.41@114.554,80.01 U2.41@114.3,79.756 ; U2.41@114.554,81.01 NT2.1@114.554,81.661 ; v9(114.859,79.197) U2.41@114.3,79.756 ; U2.41@115.05,78.306 U2.17@115.05,76.856 115.05,75.158 115.532,74.676 115.697,74.676
  Top Layer w0.35: C14.2@39.713,73.914 39.738,73.914 40.368,74.544 40.368,74.959
  Top Layer w0.5: C56.2@112.775,74.134 112.8,74.134 113.444,74.778 113.444,75.407
  other v2: 84.201,6.35 85.217,6.35 86.233,6.35 87.249,6.35 88.265,6.35 89.281,6.35 90.551,6.35 91.567,6.35 92.583,6.35 93.599,6.35 94.615,6.35 95.631,6.35 84.201,7.366 85.217,7.366 86.233,7.366 87.249,7.366 88.265,7.366 89.281,7.366 90.551,7.366 91.567,7.366 92.583,7.366 93.599,7.366 94.615,7.366 95.631,7.366 84.201,8.382 85.217,8.382 86.233,8.382 87.249,8.382 88.265,8.382 89.281,8.382 90.551,8.382 91.567,8.382 92.583,8.382 93.599,8.382 94.615,8.382 95.631,8.382 84.201,9.398 85.217,9.398 86.233,9.398 87.249,9.398 88.265,9.398 89.281,9.398 90.551,9.398 91.567,9.398 92.583,9.398 93.599,9.398 94.615,9.398 95.631,9.398 84.074,20.447 95.758,20.447 84.074,21.463 95.758,21.463 84.074,22.479 85.09,22.479 86.106,22.479 93.726,22.479 94.742,22.479 95.758,22.479 62.992,113.157 64.135,113.157 69.85,113.157 70.993,113.157 62.992,114.3 70.993,114.3 62.992,122.428 70.993,122.428 62.992,123.571 64.135,123.571 69.85,123.571 70.993,123.571 62.992,124.714 64.135,124.714 65.278,124.714 66.421,124.714 67.564,124.714 68.707,124.714 69.85,124.714 70.993,124.714 62.992,125.857 64.135,125.857 65.278,125.857 66.421,125.857 67.564,125.857 68.707,125.857 69.85,125.857 70.993,125.857
  other v3: 25.4,15.24 27.94,15.24 30.48,15.24 52.07,15.24 54.61,15.24 57.15,15.24 100.33,15.24 102.87,15.24 105.41,15.24 128.27,15.24 130.81,15.24 133.35,15.24 13.97,25.4 39.37,25.4 41.91,25.4 68.58,25.4 87.63,25.4 114.3,25.4 116.84,25.4 143.51,25.4 13.97,27.94 39.37,27.94 41.91,27.94 68.58,27.94 87.63,27.94 114.3,27.94 116.84,27.94 143.51,27.94 13.97,30.48 38.1,30.48 43.18,30.48 68.58,30.48 87.63,30.48 114.3,30.48 116.84,30.48 143.51,30.48 71.792,61.212 86.713,67.275
  other v4: 69.215,67.23 144.167,67.398 13.208,67.437 107.028,67.81 70.09,68.604 86.741,68.961 144.721,69.053 98.685,69.088 12.319,69.215 70.104,70.231 11.43,70.993 145.678,70.993 70.104,71.755 57.661,71.923 11.43,72.263 132.948,72.436 145.678,72.436 11.43,73.66 132.877,73.694 57.623,73.802 98.787,74.11 145.678,74.16 98.806,75.692 57.604,75.772 85.725,76.327 71.792,76.786 58.225,77.001 86.995,77.47 72.39,79.502 71.501,80.626 72.468,84.299
  other v5: 29.21,67.31 52.07,67.31 54.61,67.31 57.15,67.31 101.6,67.31 104.14,67.31 129.54,67.31 132.08,67.31 27.94,68.58 30.48,68.58 53.34,68.58 55.88,68.58 102.87,68.58 128.27,68.58 130.81,68.58
  other v9: 40.589,78.257 41.707,78.257 113.741,78.41 114.859,78.41 39.802,79.045 40.589,79.045 41.707,79.045 42.494,79.045 112.954,79.197 115.646,79.197 39.802,80.162 40.589,80.162 41.707,80.162 42.494,80.162 112.954,80.315 115.646,80.315 113.725,80.331 114.875,80.331 40.589,80.924 41.707,80.924 113.741,81.102 114.859,81.102
  other v13: 26.67,67.31
SS: C49.1 U1.1 U1.30 U2.1 U2.30 | length 100
  Top Layer w0.25: v7(36.103,83.888) 36.198,83.888 36.4,83.686 36.932,83.686 37.298,83.32 37.298,82.621 38.073,81.846 U1.1@38.248,81.846 ; U1.30@44.048,81.846 44.613,81.846 45.085,82.319 45.085,82.321 ; v7(110.498,82.656) 110.498,82.561 110.678,82.381 110.678,82.262 110.934,82.006 U2.1@111.4,82.006 ; U2.30@117.2,82.006 117.914,82.006 118.17,82.262 118.17,82.61 v7(118.237,82.677)
  Top Layer w0.35: 45.085,82.321 45.085,82.66 47.375,84.949 v15(47.375,85.017) C49.1@47.375,85.767
  Layer 3 w0.35: v7(36.103,83.888) 36.151,83.936 38.162,83.936 39.243,85.017 v15(47.375,85.017) 47.443,85.017 48.151,85.725 73.55,85.725 77.982,90.157 95.825,90.157 101.655,84.328 104.179,84.328 105.203,83.304 105.203,82.861 105.408,82.656 v7(110.498,82.656) 110.509,82.666 118.226,82.666 v7(118.237,82.677)
SYNC: U1.39 U2.33 | length 92.1
  Top Layer w0.25: v7(36.987,84.845) 37.082,84.845 38.111,83.816 38.705,83.816 39.398,83.123 U1.39@39.398,82.496 ; U2.33@115.55,82.656 115.55,83.196 115.766,83.412 115.766,83.778 115.983,83.995 115.983,84.794 v7(116.05,84.861)
  Layer 3 w0.4: v7(36.987,84.845) 37.026,84.884 37.026,86.072 39.205,88.252 44.799,88.252 46.155,86.896 72.954,86.896 77.052,90.995 96.509,90.995 102.313,85.191 115.382,85.191 115.674,84.899 116.012,84.899 v7(116.05,84.861)
UVLO: C51.1 J6.2 R20.1 R21.2 R26.1 R31.2 R51.1 R52.2 | length 102.7
  Top Layer w0.35: C51.1@26.209,88.159 26.259,88.209 27.683,88.209 R31.2@27.733,88.259 27.746,88.272 29.271,88.272 R26.1@29.284,88.285 29.287,88.288 30.277,88.288 v8(30.28,88.291) ; R21.2@35.388,87.527 35.41,87.55 35.41,88.242 v8(35.433,88.265) ; v8(45.847,88.265) 45.849,88.263 45.849,87.369 R20.1@45.851,87.367 ; R52.2@110.363,87.414 v8(110.363,88.164) ; R51.1@117.602,87.414 v8(117.602,88.164)
  Top Layer w0.5: J6.2@22.691,88.983 25.36,88.983 26.184,88.159 C51.1@26.209,88.159
  Layer 3 w0.35: v8(30.28,88.291) 30.293,88.278 35.42,88.278 v8(35.433,88.265) 35.528,88.265 36.405,89.143 44.875,89.143 45.752,88.265 73.026,88.265 77.217,92.456 96.566,92.456 100.858,88.164 v8(110.363,88.164) v8(117.602,88.164)
VCC1: C14.1 D1.2 D2.2 U1.15 U1.16 | length 8.5
  Top Layer w0.25: U1.15@40.898,76.696 40.898,76.216 41.063,76.051 41.252,76.051 41.398,76.197 U1.16@41.398,76.696
  Top Layer w0.5: D2.2@40.483,71.641 D2.2@40.47,71.628 41.593,71.628 D1.2@42.715,71.628 D1.2@42.702,71.641 ; C14.1@41.252,73.975 C14.1@41.313,73.914
  Top Layer w0.7: C14.1@41.252,73.975 41.252,76.051 ; C14.1@41.313,73.914 41.338,73.914 41.463,73.789 41.463,71.757 41.593,71.628
VCC2: C56.1 D5.2 D6.2 U2.15 U2.16 | length 8.9
  Top Layer w0.25: U2.15@114.05,76.856 114.05,76.275 114.15,76.175 114.289,76.175 114.427,76.175 114.55,76.298 U2.16@114.55,76.856
  Top Layer w0.6: D6.2@113.325,71.882 114.375,71.882 D5.2@116.121,71.882 ; C56.1@114.289,74.22 C56.1@114.375,74.134
  Top Layer w0.7: C56.1@114.289,74.22 114.289,76.175 ; 114.375,71.882 C56.1@114.375,74.134
VDDA1: C13.2 R24.2 U1.34 U1.36 U1.38 | length 13.7
  Top Layer w0.25: v7(39.523,84.093) 39.48,84.05 39.48,83.678 39.898,83.26 U1.38@39.898,82.496 ; C13.2@40.373,86.027 40.375,86.025 40.375,84.952 40.898,84.429 U1.36@40.898,82.496 ; U1.34@41.898,82.496 41.898,83.648 42.205,83.955 v7(42.205,84.05)
  Top Layer w0.4: R24.2@38.608,85.941 38.646,85.979 39.516,85.979 v7(39.554,86.017) 39.559,86.022 40.368,86.022 C13.2@40.373,86.027
  Layer 3 w0.4: v7(39.523,84.093) 39.545,84.071 42.183,84.071 v7(42.205,84.05)
  Bottom Layer w0.25: v7@39.538,84.108 v7(39.523,84.093) v7@39.545,84.071 ; v7@39.538,86.002 v7(39.554,86.017) ; v7@42.183,84.071 v7(42.205,84.05)
  Bottom Layer w0.4: v7@39.538,84.108 v7@39.538,86.002
VDDA2: C55.2 R53.2 U2.3 U2.34 U2.36 U2.38 | length 33
  Top Layer w0.25: v7(110.109,81.153) 110.204,81.153 110.351,81.006 U2.3@111.4,81.006 ; v7(112.55,83.66) 112.594,83.66 113.05,83.204 U2.38@113.05,82.656 ; 113.725,84.328 114.05,84.003 U2.36@114.05,82.656 ; U2.34@115.05,82.656 115.05,83.332 115.316,83.598 v7(115.316,84.267)
  Top Layer w0.35: 113.725,84.328 113.411,84.642 C55.2@113.411,85.787 113.411,86.106 v8(114.046,86.106)
  Top Layer w0.4: R53.2@121.031,87.414 121.031,87.362 v8(121.756,87.362)
  Layer 3 w0.35: v7(112.55,83.66) v7@112.618,83.66 ; v7@115.268,84.22 v7(115.316,84.267)
  Layer 3 w0.4: v8(114.046,86.106) 114.103,86.163 120.476,86.163 121.675,87.362 v8(121.756,87.362)
  Bottom Layer w0.35: v7(112.55,83.66) 112.598,83.708 112.598,84.563 114.046,86.011 v8(114.046,86.106) 114.141,86.106 114.743,85.503 114.78,85.503 115.316,84.967 v7(115.316,84.267)
  Bottom Layer w0.4: v7(110.109,81.153) 109.219,81.153 108.674,81.698 108.674,83.185 111.537,86.049 113.989,86.049 v8(114.046,86.106)
VIN: C8.2 C9.1 C10.1 C12.1 C15.1 C16.1 C17.1 C18.1 C19.1 C20.2 C21.2 C22.2 C23.2 C24.1 C25.1 C26.1 C27.1 C28.1 C54.1 C57.1 C58.1 C59.1 C60.1 C61.1 C62.2 C63.2 C64.2 C65.2 C66.1 C67.1 C68.1 C69.1 C70.1 L2.2 Q1.5 Q2.5 Q5.5 Q6.5 R26.2 TP2.1 U1.25 U2.25 | length 60.6
  Top Layer w0.25: U1.25@44.048,79.346 45.526,79.346 45.851,79.021 ; U2.25@117.2,79.506 118.322,79.506 118.631,79.197
  Top Layer w0.35: 45.851,79.021 46.41,79.021 49.102,76.329 C12.1@49.102,76.164
  Top Layer w0.4: 118.631,79.197 119.215,79.197 121.92,76.492 C54.1@121.92,76.327
  Top Layer w0.5: R26.2@29.284,86.685 29.363,86.606 29.363,85.681 v8(29.402,85.643) ; C12.1@49.102,76.329 49.276,76.155 49.276,75.397 v4(49.901,74.772) ; C54.1@121.92,76.327 121.92,76.162 123.283,74.799 v1(123.283,74.795)
  Layer 3 w0.5: 19.936,76.051 19.936,82.427 23.114,85.605 29.363,85.605 v8(29.402,85.643) ; v4(49.901,74.772) 61.725,74.772 ; v1(123.283,74.795) 123.312,74.766 137.209,74.766
  other v1: 93.091,66.04 17.272,67.31 64.643,67.31 91.821,67.31 139.7,67.31 63.373,68.58 93.091,68.58 138.43,68.58 17.272,69.85 64.643,69.85 91.821,69.85 139.7,69.85 63.373,71.12 93.091,71.12 138.43,71.12 17.272,72.39 64.643,72.39 91.821,72.39 139.7,72.39 63.373,73.66 93.091,73.66 138.43,73.66 17.272,74.93 64.643,74.93 91.821,74.93 139.7,74.93 63.367,76.116 93.091,76.2 138.43,76.2 77.47,77.47 80.01,77.47 82.55,77.47 78.74,78.74 81.28,78.74 83.82,78.827 77.47,80.01 80.01,80.01 82.55,80.01 85.09,80.01 87.63,80.01 90.17,80.01 92.71,80.01 95.25,80.01 83.82,81.28 86.36,81.28 88.9,81.28 91.44,81.28 93.98,81.28 85.09,82.55 87.63,82.55 90.17,82.55 92.71,82.55 95.25,82.55 83.82,83.82 86.36,83.82 88.9,83.82 91.44,83.82 93.98,83.82 85.09,85.09 87.63,85.09 90.17,85.09 92.71,85.09 95.25,85.09 86.36,86.36 88.9,86.36 91.44,86.36 93.98,86.36
  other v4: 18.542,68.58 18.542,71.12 18.542,73.66 18.542,76.2
  other v5: 62.103,61.849 63.373,61.849 64.643,61.849 91.821,61.849 93.091,61.849 94.361,61.849 17.362,61.863 18.632,61.863 19.902,61.863 62.103,63.119 63.373,63.119 64.643,63.119 91.821,63.119 93.091,63.119 94.361,63.119 17.362,63.133 18.632,63.133 19.902,63.133 94.361,64.35 62.103,64.389 63.373,64.389 64.643,64.389 91.821,64.389 93.091,64.389 17.362,64.403 18.632,64.403 19.902,64.403
  other v6: 137.033,61.849 138.303,61.849 139.573,61.849 137.033,63.119 138.303,63.119 139.573,63.119 137.033,64.389 138.303,64.389 139.573,64.389
VOUT: C35.1 C36.1 C37.1 C38.1 C39.1 C40.2 C41.2 C42.1 C43.1 C44.1 C73.1 C78.1 C79.1 C80.1 C81.1 C82.2 C83.2 C84.1 C85.1 C86.1 J4.1 R6.1 R7.2 R10.2 R13.2 R23.2 R37.1 R38.2 R41.2 R44.2 R61.1 R71.2 R371.1 R381.2 TP4.1 | length 415
  Top Layer w0.254: 30.48,30.48 R71.2@30.48,31.347
  Top Layer w0.3: R7.2@24.003,30.812 v12(24.003,31.877)
  Top Layer w0.35: R10.2@50.601,79.394 50.788,79.581 52.784,79.581 v7(52.832,79.629) ; R6.1@57.658,30.812 v12(57.658,31.877) ; R38.2@98.298,30.939 v11(98.298,32.004) ; R37.1@132.715,30.939 v11(132.715,32.004)
  Top Layer w0.4: v8(30.226,81.153) 30.233,81.146 32.571,81.146 R13.2@32.578,81.139 ; v8(60.699,84.558) 60.703,84.561 60.703,85.543 R23.2@60.706,85.546 ; v6(102.743,80.645) 102.824,80.645 103.134,80.955 104.545,80.955 104.899,80.601 104.924,80.601 105.124,80.401 R44.2@105.124,80.376 ; R41.2@124.271,79.629 124.311,79.589 126.19,79.589 126.23,79.629 126.411,79.629 126.665,79.883 v8(126.746,79.883)
  Top Layer w0.5: J4.1@64.884,6.21 v2(66.04,7.366) v2(67.056,8.382) v2(68.072,9.398) 70.739,12.065 J4.1@70.739,16.637
  Bottom Layer w0.25: v12(24.003,31.877) v12@24.003,31.999
  Bottom Layer w0.3: v12@24.003,31.999 24.928,32.924 24.928,33.806 5.969,52.765 5.969,72.63 14.492,81.153 v8(30.226,81.153)
  Bottom Layer w0.35: v7(52.832,79.629) 66.783,79.629 73.914,72.498 73.914,70.041 75.517,68.437 75.517,49.133 69.564,43.18 63.553,43.18 56.388,36.015 56.388,32.385 56.896,31.877 v12(57.658,31.877) ; v11(98.298,32.004) 98.298,32.099 99.223,33.024 99.223,33.528 82.042,50.709 82.042,69.741 90.871,78.57 98.74,78.57 101.214,81.044 102.263,81.044 102.662,80.645 v6(102.743,80.645) ; v8(126.746,79.883) 145.161,79.883 149.352,75.692 149.352,49.245 139.356,39.249 136.785,39.249 131.731,34.195 131.731,32.893 132.62,32.004 v11(132.715,32.004)
  Bottom Layer w0.4: v8(60.699,84.558) 60.756,84.501 65.45,84.501 79.06,70.891 79.06,43.944 81.135,41.869 81.135,33.569 79.06,31.494 79.06,17.719 77.978,16.637 J4.1@75.65,16.637 ; v2(76.454,6.35) J4.1@76.889,5.915
  other v1: 20.32,25.4 22.86,25.4 30.48,25.4 33.02,25.4 49.53,25.4 52.07,25.4 59.69,25.4 95.25,25.4 97.79,25.4 105.41,25.4 107.95,25.4 123.19,25.4 125.73,25.4 133.35,25.4 135.89,25.4 21.59,26.67 24.13,26.67 31.75,26.67 50.8,26.67 55.88,26.67 58.42,26.67 60.96,26.67 96.52,26.67 99.06,26.67 106.68,26.67 124.46,26.67 127,26.67 132.08,26.67 134.62,26.67 20.32,27.94 22.86,27.94 30.48,27.94 33.02,27.94 49.53,27.94 52.07,27.94 59.69,27.94 95.25,27.94 97.79,27.94 105.41,27.94 107.95,27.94 123.19,27.94 125.73,27.94 133.35,27.94 135.89,27.94 21.59,29.21 24.13,29.21 26.67,29.21 29.21,29.21 31.75,29.21 50.8,29.21 53.34,29.21 55.88,29.21 58.42,29.21 60.96,29.21 96.52,29.21 104.14,29.21 106.68,29.21 124.46,29.21 127,29.21 132.08,29.21 134.62,29.21 20.32,30.48 27.94,30.48 33.02,30.48 49.53,30.48 52.07,30.48 54.61,30.48 59.69,30.48 95.25,30.48 105.41,30.48 107.95,30.48 123.19,30.48 125.73,30.48 128.27,30.48 130.81,30.48 135.89,30.48
  other v2: 65.024,6.35 66.04,6.35 67.056,6.35 68.072,6.35 69.088,6.35 70.104,6.35 71.374,6.35 72.39,6.35 73.406,6.35 74.422,6.35 75.438,6.35 65.024,7.366 67.056,7.366 68.072,7.366 69.088,7.366 70.104,7.366 71.374,7.366 72.39,7.366 73.406,7.366 74.422,7.366 75.438,7.366 76.454,7.366 65.024,8.382 66.04,8.382 68.072,8.382 69.088,8.382 70.104,8.382 71.374,8.382 72.39,8.382 73.406,8.382 74.422,8.382 75.438,8.382 76.454,8.382 65.024,9.398 66.04,9.398 67.056,9.398 69.088,9.398 70.104,9.398 71.374,9.398 72.39,9.398 73.406,9.398 74.422,9.398 75.438,9.398 76.454,9.398 64.897,20.447 76.581,20.447 64.897,21.463 76.581,21.463 64.897,22.479 65.913,22.479 66.929,22.479 74.549,22.479 75.565,22.479 76.581,22.479
  other v3: 100.33,25.4 100.311,27.856 101.6,29.21 100.33,30.48 102.87,30.48
  other v4: 25.407,25.299 57.15,25.4 62.23,25.4 128.27,25.4 48.26,26.67 137.16,26.67 25.4,27.94 57.15,27.94 62.23,27.94 128.27,27.94 48.26,29.21 99.06,29.21 129.54,29.21 137.16,29.21 25.4,30.48 62.23,30.48 97.79,30.48
pads on no net: U1.7 U1.24 U2.7 U2.24 U2.39

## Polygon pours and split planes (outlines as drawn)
AGND2 on Top Layer "TOP_LAYER_AGND2_P000" (solid, remove dead copper, pour order 0): 108.458,92.456 122.645,92.456 122.645,84.003 108.458,84.003 108.458,84.201
VOUT on Top Layer "TOP_LAYER_VOUT_P001" (solid, remove dead copper, pour order 1): 120.827,32.258 139.065,32.258 139.065,24.257 120.904,24.257
NetC74_2 on Top Layer "TOP_LAYER_NETC74_2_P004" (solid, remove dead copper, pour order 4): 138.336,46.482 139.065,45.753 139.065,34.974 137.106,33.015 122.805,33.015 120.896,34.925 120.896,44.922 122.456,46.482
